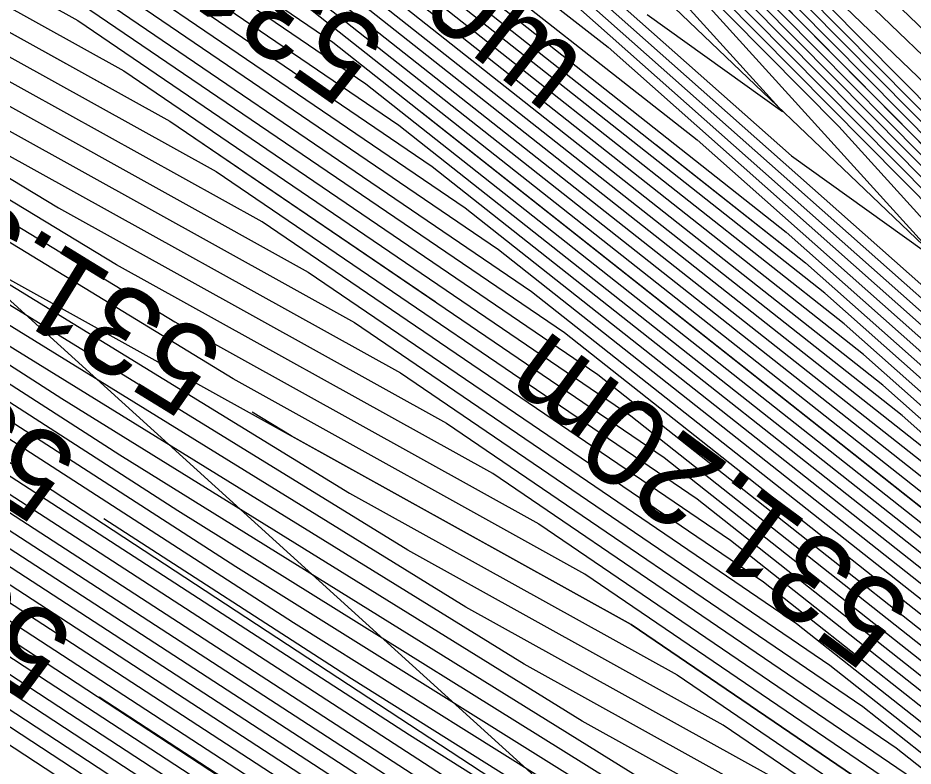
# Model space of a CAD drawing. Extents: x -866683 to -866410, y -1041951 to -1040252.
# Drawn here: x -866436.676 to -866433.64, y -1041922.966 to -1041920.429 of the extents above; entities that cross this region are included whole.
import ezdxf

# ---------------------------------------------------------------- set-up
doc = ezdxf.new("R2010")
doc.units = 0
for name, color, linetype in [('BREAKLINE', 7, 'Continuous'), ('V-HL', 7, 'Continuous'), ('V-VEDL', 7, 'Continuous'), ('V_po_cm', 7, 'Continuous')]:
    doc.layers.add(name, color=color, linetype=linetype)

msp = doc.modelspace()

# ---------------------------------------------------------------- linework, layer by layer
at = {"layer": 'BREAKLINE'}
for points in [[(-866445.626, -1041911.77), (-866438.844, -1041916.202), (-866428.169, -1041926.387)], [(-866430.202, -1041927.282), (-866445.247, -1041913.64), (-866449.543, -1041926.354), (-866449.641, -1041934.033), (-866450.183, -1041936.864), (-866452.267, -1041937.851), (-866451.576, -1041945.087)]]:
    msp.add_lwpolyline(points, dxfattribs=at)
at = {"layer": 'V-HL'}
for points in [[(-866432.13, -1041922.3514), (-866435.3498, -1041919.1014), (-866436.3778, -1041918.1143)], [(-866435.9248, -1041919.7422), (-866434.0049, -1041921.2589), (-866431.3462, -1041923.6159)]]:
    msp.add_lwpolyline(points, dxfattribs=at)
at = {"layer": 'V-VEDL'}
for points in [[(-866449.345, -1041907.5366), (-866448.9556, -1041907.8532), (-866448.4862, -1041908.0339), (-866448.3105, -1041908.3809), (-866448.4285, -1041908.8942), (-866448.8402, -1041909.5738), (-866449.0019, -1041910.1655), (-866448.9134, -1041910.6692), (-866448.5749, -1041911.085), (-866448.5335, -1041911.4362), (-866448.7893, -1041911.7228), (-866449.3421, -1041911.9448), (-866449.4057, -1041912.585), (-866448.98, -1041913.6435), (-866448.0652, -1041915.1203), (-866447.345, -1041916.0757), (-866446.8195, -1041916.5099), (-866446.4887, -1041916.4228), (-866444.7099, -1041917.3864), (-866441.483, -1041919.4008), (-866432.1333, -1041925.5308)], [(-866446.5999, -1041908.6762), (-866447.0916, -1041908.5269), (-866447.2852, -1041908.4542), (-866447.4265, -1041908.3834), (-866447.5156, -1041908.3147), (-866447.7197, -1041908.5079), (-866448.039, -1041908.963), (-866448.4735, -1041909.6802), (-866448.6281, -1041910.3241), (-866448.5029, -1041910.8948), (-866448.0979, -1041911.3922), (-866447.9787, -1041911.7844), (-866448.1452, -1041912.0714), (-866448.5975, -1041912.253), (-866448.6496, -1041912.7768), (-866448.3013, -1041913.6429), (-866447.5528, -1041914.8511), (-866446.9635, -1041915.6329), (-866446.5336, -1041915.9881), (-866446.2629, -1041915.9168), (-866444.8075, -1041916.7053), (-866442.1674, -1041918.3533), (-866434.5176, -1041923.3688)], [(-866441.6705, -1041916.8829), (-866437.7247, -1041919.072), (-866435.6089, -1041920.5114), (-866433.3503, -1041922.2956), (-866428.5474, -1041926.5536)], [(-866439.2862, -1041919.0449), (-866436.1607, -1041920.7789), (-866434.4848, -1041921.919), (-866432.6958, -1041923.3322), (-866428.8914, -1041926.705)], [(-866436.9019, -1041921.2069), (-866434.5968, -1041922.4857), (-866433.3607, -1041923.3266), (-866432.0413, -1041924.3689), (-866429.2354, -1041926.8565)]]:
    msp.add_lwpolyline(points, dxfattribs=at)
at = {"layer": 'V_po_cm'}
msp.add_lwpolyline([(-866447.3599, -1041911.0448), (-866445.9513, -1041912.7749), (-866444.619, -1041913.8303), (-866442.6588, -1041915.0759), (-866440.0707, -1041916.5117), (-866437.6107, -1041918.1202), (-866435.2789, -1041919.9012), (-866433.0752, -1041921.8549), (-866432.4602, -1041922.2952), (-866433.4339, -1041921.2221), (-866435.9962, -1041918.6357), (-866438.0089, -1041916.6902), (-866439.4718, -1041915.3858), (-866440.3849, -1041914.7224), (-866441.4494, -1041913.9281), (-866442.665, -1041913.0029), (-866444.032, -1041911.9468), (-866445.0847, -1041911.1336), (-866445.8231, -1041910.5632), (-866446.2472, -1041910.2357), (-866446.6064, -1041910.1437), (-866446.9008, -1041910.2871)], close=True, dxfattribs=at)
for points in [[(-866449.4813, -1041912.5658), (-866449.0479, -1041913.6436), (-866448.1164, -1041915.1472), (-866447.3831, -1041916.12), (-866446.8481, -1041916.5621), (-866446.5112, -1041916.4734), (-866444.7001, -1041917.4545), (-866441.4146, -1041919.5055), (-866436.6547, -1041922.6262), (-866433.3844, -1041924.7606), (-866431.6036, -1041925.9086), (-866431.3124, -1041926.0701), (-866431.0001, -1041926.2826), (-866430.6667, -1041926.546), (-866429.9578, -1041927.1745)], [(-866449.3301, -1041912.6042), (-866448.9122, -1041913.6435), (-866448.0139, -1041915.0933), (-866447.3068, -1041916.0314), (-866446.7909, -1041916.4577), (-866446.4661, -1041916.3722), (-866444.7196, -1041917.3183), (-866441.5514, -1041919.296), (-866436.9616, -1041922.3053), (-866433.7773, -1041924.3805), (-866431.9985, -1041925.5217), (-866431.6252, -1041925.7288), (-866431.2249, -1041926.0011), (-866430.7976, -1041926.3386), (-866429.889, -1041927.1442)], [(-866429.8546, -1041927.129), (-866430.8631, -1041926.2349), (-866431.3373, -1041925.8603), (-866431.7816, -1041925.5581), (-866432.1959, -1041925.3282), (-866433.9737, -1041924.1905), (-866437.115, -1041922.1448), (-866441.6199, -1041919.1913), (-866444.7294, -1041917.2502), (-866446.4435, -1041916.3216), (-866446.7623, -1041916.4055), (-866447.2687, -1041915.9871), (-866447.9627, -1041915.0664), (-866448.8443, -1041913.6434), (-866449.2545, -1041912.6234)], [(-866429.8202, -1041927.1139), (-866430.9285, -1041926.1313), (-866431.4498, -1041925.7195), (-866431.938, -1041925.3874), (-866432.3933, -1041925.1348), (-866434.1701, -1041924.0005), (-866437.2685, -1041921.9844), (-866441.6883, -1041919.0865), (-866444.7391, -1041917.1821), (-866446.4209, -1041916.271), (-866446.7337, -1041916.3534), (-866447.2305, -1041915.9429), (-866447.9114, -1041915.0395), (-866448.7764, -1041913.6433), (-866449.1788, -1041912.6426)], [(-866449.3873, -1041913.6439), (-866448.3726, -1041915.2817), (-866447.5738, -1041916.3414), (-866446.991, -1041916.823), (-866446.6241, -1041916.7264), (-866444.6513, -1041917.7951), (-866441.0724, -1041920.0292), (-866435.8875, -1041923.4286), (-866432.4023, -1041925.7108), (-866430.6166, -1041926.8758), (-866430.5304, -1041926.9236), (-866430.4381, -1041926.9864), (-866430.3395, -1041927.0643), (-866430.1298, -1041927.2502)], [(-866430.0954, -1041927.2351), (-866430.4049, -1041926.9606), (-866430.5505, -1041926.8456), (-866430.6868, -1041926.7529), (-866430.814, -1041926.6823), (-866432.5987, -1041925.5207), (-866436.041, -1041923.2681), (-866441.1408, -1041919.9245), (-866444.661, -1041917.727), (-866446.6015, -1041916.6758), (-866446.9624, -1041916.7708), (-866447.5357, -1041916.2972), (-866448.3213, -1041915.2548), (-866449.3194, -1041913.6438)], [(-866449.2515, -1041913.6438), (-866448.2701, -1041915.2279), (-866447.4975, -1041916.2529), (-866446.9338, -1041916.7186), (-866446.579, -1041916.6252), (-866444.6708, -1041917.6589), (-866441.2093, -1041919.8197), (-866436.1944, -1041923.1077), (-866432.7951, -1041925.3307), (-866431.0114, -1041926.4889), (-866430.8432, -1041926.5822), (-866430.6629, -1041926.7049), (-866430.4704, -1041926.857), (-866430.061, -1041927.2199)], [(-866430.0266, -1041927.2048), (-866430.5358, -1041926.7533), (-866430.7753, -1041926.5641), (-866430.9996, -1041926.4115), (-866431.2088, -1041926.2954), (-866432.9916, -1041925.1407), (-866436.3479, -1041922.9472), (-866441.2777, -1041919.715), (-866444.6806, -1041917.5908), (-866446.5564, -1041916.5746), (-866446.9052, -1041916.6664), (-866447.4594, -1041916.2086), (-866448.2189, -1041915.201), (-866449.1837, -1041913.6437)], [(-866449.1158, -1041913.6437), (-866448.1676, -1041915.1741), (-866447.4212, -1041916.1643), (-866446.8766, -1041916.6143), (-866446.5338, -1041916.524), (-866444.6903, -1041917.5227), (-866441.3461, -1041919.6102), (-866436.5013, -1041922.7867), (-866433.188, -1041924.9506), (-866431.4062, -1041926.102), (-866431.156, -1041926.2408), (-866430.8877, -1041926.4234), (-866430.6013, -1041926.6496), (-866429.9922, -1041927.1896)], [(-866436.6255, -1041917.6643), (-866433.1945, -1041921.1275)], [(-866427.7667, -1041926.0662), (-866436.2098, -1041917.9718)], [(-866436.3065, -1041918.0236), (-866432.1894, -1041922.1794)], [(-866429.5106, -1041926.9776), (-866431.5176, -1041925.1983), (-866432.4615, -1041924.4527), (-866433.3456, -1041923.8512), (-866434.17, -1041923.3938), (-866435.9379, -1041922.2901), (-866438.6494, -1041920.5402), (-866442.3042, -1041918.1439)], [(-866429.545, -1041926.9928), (-866431.4522, -1041925.3019), (-866432.349, -1041924.5935), (-866433.1892, -1041924.0219), (-866433.9726, -1041923.5873), (-866435.7415, -1041922.4802), (-866438.4959, -1041920.7006), (-866442.2358, -1041918.2486)], [(-866435.9876, -1041918.3828), (-866431.1843, -1041923.2313)], [(-866435.581, -1041919.5877), (-866433.5641, -1041921.3758), (-866433.0012, -1041921.7788), (-866433.8924, -1041920.7967), (-866436.2376, -1041918.4294)], [(-866429.6138, -1041927.023), (-866431.3213, -1041925.5093), (-866432.1242, -1041924.875), (-866432.8764, -1041924.3633), (-866433.5778, -1041923.9742), (-866435.3487, -1041922.8603), (-866438.1891, -1041921.0216), (-866442.0989, -1041918.4581)], [(-866437.2281, -1041918.5416), (-866434.6746, -1041920.5282), (-866432.0974, -1041922.813), (-866431.3782, -1041923.3279), (-866432.5169, -1041922.073), (-866435.5136, -1041919.0482)], [(-866429.6482, -1041927.0382), (-866431.2558, -1041925.6129), (-866432.0118, -1041925.0157), (-866432.72, -1041924.534), (-866433.3804, -1041924.1676), (-866435.1522, -1041923.0503), (-866438.0356, -1041921.182), (-866442.0305, -1041918.5628)], [(-866441.9621, -1041918.6676), (-866437.8822, -1041921.3425), (-866434.9558, -1041923.2403), (-866433.183, -1041924.361), (-866432.5636, -1041924.7046), (-866431.8994, -1041925.1565), (-866431.1904, -1041925.7166), (-866429.6826, -1041927.0533)], [(-866437.0368, -1041918.7523), (-866434.3725, -1041920.8417), (-866431.6085, -1041923.292), (-866430.8372, -1041923.8443), (-866432.0584, -1041922.4984), (-866435.2722, -1041919.2544)], [(-866435.6687, -1041918.7421), (-866430.1792, -1041924.2832)], [(-866429.717, -1041927.0685), (-866431.1249, -1041925.8203), (-866431.787, -1041925.2973), (-866432.4072, -1041924.8753), (-866432.9855, -1041924.5545), (-866434.7594, -1041923.4304), (-866437.7288, -1041921.503), (-866441.8936, -1041918.7723)], [(-866434.9767, -1041920.2147), (-866432.5863, -1041922.3339), (-866431.9192, -1041922.8115), (-866432.9754, -1041921.6475), (-866435.7549, -1041918.8419)], [(-866429.7514, -1041927.0836), (-866431.0594, -1041925.9239), (-866431.6746, -1041925.438), (-866432.2508, -1041925.046), (-866432.7881, -1041924.7479), (-866434.563, -1041923.6204), (-866437.5753, -1041921.6634), (-866441.8252, -1041918.877)], [(-866436.8455, -1041918.963), (-866434.0703, -1041921.1552), (-866431.1197, -1041923.7711), (-866430.2962, -1041924.3606), (-866431.6, -1041922.9238), (-866435.0309, -1041919.4606)], [(-866429.7858, -1041927.0988), (-866430.994, -1041926.0276), (-866431.5622, -1041925.5788), (-866432.0944, -1041925.2167), (-866432.5907, -1041924.9414), (-866434.3665, -1041923.8104), (-866437.4219, -1041921.8239), (-866441.7568, -1041918.9818)], [(-866427.817, -1041926.1063), (-866435.2047, -1041919.0237)], [(-866429.201, -1041926.8413), (-866432.1067, -1041924.2653), (-866433.4731, -1041923.1858), (-866434.7532, -1041922.315), (-866435.9468, -1041921.6529), (-866437.7058, -1041920.5798), (-866440.0303, -1041919.0959)], [(-866438.8617, -1041919.234), (-866437.7235, -1041919.9119), (-866436.1607, -1041920.7789), (-866435.2618, -1041921.3904)], [(-866437.5683, -1041919.2427), (-866435.4965, -1041920.6521), (-866433.2849, -1041922.3992), (-866428.5818, -1041926.5687)], [(-866428.2378, -1041926.4173), (-866433.9394, -1041921.3625), (-866436.6206, -1041919.2445)], [(-866435.8831, -1041919.2742), (-866434.053, -1041920.8968), (-866433.5422, -1041921.2624), (-866434.3509, -1041920.3712)], [(-866428.2722, -1041926.4324), (-866433.874, -1041921.4662), (-866436.5082, -1041919.3853)], [(-866439.7234, -1041919.4169), (-866437.3129, -1041920.9599), (-866435.5519, -1041922.0397), (-866434.4404, -1041922.6564), (-866433.2483, -1041923.4674), (-866431.9758, -1041924.4726), (-866429.2698, -1041926.8716)], [(-866437.4119, -1041919.4134), (-866435.3841, -1041920.7929), (-866433.2194, -1041922.5029), (-866428.6162, -1041926.5839)], [(-866438.8843, -1041919.4396), (-866437.1312, -1041920.4922), (-866435.6915, -1041921.2909), (-866434.1476, -1041922.3413), (-866432.4994, -1041923.6432), (-866428.9946, -1041926.7505)], [(-866438.1183, -1041919.525), (-866436.4735, -1041920.4375), (-866434.7097, -1041921.6375), (-866432.8267, -1041923.1249), (-866428.8226, -1041926.6747)], [(-866428.3066, -1041926.4476), (-866433.8085, -1041921.5699), (-866436.3958, -1041919.526)], [(-866429.3042, -1041926.8867), (-866431.9103, -1041924.5763), (-866433.1359, -1041923.6081), (-866434.284, -1041922.8271), (-866435.3545, -1041922.2332), (-866437.1165, -1041921.1499), (-866439.57, -1041919.5773)], [(-866428.6506, -1041926.599), (-866433.154, -1041922.6066), (-866435.2717, -1041920.9337), (-866437.2555, -1041919.5841)], [(-866438.6879, -1041919.6296), (-866436.9338, -1041920.6857), (-866435.5351, -1041921.4616), (-866434.0352, -1041922.482), (-866432.434, -1041923.7469), (-866429.029, -1041926.7656)], [(-866428.341, -1041926.4627), (-866433.7431, -1041921.6735), (-866436.2834, -1041919.6668)], [(-866437.9209, -1041919.7184), (-866436.3171, -1041920.6082), (-866434.5973, -1041921.7782), (-866432.7612, -1041923.2286), (-866428.857, -1041926.6899)], [(-866429.3386, -1041926.9019), (-866431.8449, -1041924.6799), (-866433.0235, -1041923.7489), (-866434.1276, -1041922.9978), (-866435.1571, -1041922.4266), (-866436.9201, -1041921.34), (-866439.4165, -1041919.7378)], [(-866428.685, -1041926.6142), (-866433.0885, -1041922.7102), (-866435.1593, -1041921.0744), (-866437.0991, -1041919.7548)], [(-866438.4915, -1041919.8197), (-866436.7364, -1041920.8791), (-866435.3788, -1041921.6323), (-866433.9228, -1041922.6228), (-866432.3685, -1041923.8506), (-866429.0634, -1041926.7807)], [(-866428.3754, -1041926.4779), (-866433.6776, -1041921.7772), (-866436.171, -1041919.8076)], [(-866429.373, -1041926.917), (-866431.7794, -1041924.7836), (-866432.9111, -1041923.8896), (-866433.9712, -1041923.1685), (-866434.9597, -1041922.6201), (-866436.7237, -1041921.53), (-866439.2631, -1041919.8983)], [(-866428.7194, -1041926.6293), (-866433.0231, -1041922.8139), (-866435.0469, -1041921.2152), (-866436.9427, -1041919.9254)], [(-866428.4098, -1041926.493), (-866433.6121, -1041921.8809), (-866436.0586, -1041919.9483)], [(-866434.5418, -1041920.4177), (-866434.0832, -1041920.7461), (-866434.8093, -1041919.9458)], [(-866431.5518, -1041922.935), (-866434.5077, -1041919.9514)], [(-866438.2951, -1041920.0097), (-866436.539, -1041921.0725), (-866435.2224, -1041921.803), (-866433.8104, -1041922.7636), (-866432.3031, -1041923.9542), (-866429.0978, -1041926.7959)], [(-866429.4074, -1041926.9322), (-866431.714, -1041924.8873), (-866432.7987, -1041924.0304), (-866433.8148, -1041923.3392), (-866434.7623, -1041922.8135), (-866436.5272, -1041921.72), (-866439.1097, -1041920.0587)], [(-866428.4442, -1041926.5082), (-866433.5467, -1041921.9845), (-866435.9462, -1041920.0891)], [(-866427.8673, -1041926.1464), (-866434.1996, -1041920.0756)], [(-866437.5261, -1041920.1053), (-866436.0043, -1041920.9496), (-866434.3724, -1041922.0597), (-866432.6303, -1041923.4359), (-866428.9258, -1041926.7202)], [(-866436.7863, -1041920.0961), (-866434.9345, -1041921.3559), (-866432.9576, -1041922.9176), (-866428.7538, -1041926.6444)], [(-866429.1322, -1041926.811), (-866432.2376, -1041924.0579), (-866433.698, -1041922.9043), (-866435.066, -1041921.9737), (-866436.3416, -1041921.266), (-866438.0986, -1041920.1998)], [(-866438.9562, -1041920.2192), (-866436.3308, -1041921.9101), (-866434.5649, -1041923.0069), (-866433.6584, -1041923.5098), (-866432.6863, -1041924.1712), (-866431.6485, -1041924.9909), (-866429.4418, -1041926.9473)], [(-866428.4786, -1041926.5233), (-866433.4812, -1041922.0882), (-866435.8338, -1041920.2298)], [(-866428.7882, -1041926.6596), (-866432.8922, -1041923.0212), (-866434.8221, -1041921.4967), (-866436.6299, -1041920.2668)], [(-866428.9602, -1041926.7353), (-866432.5649, -1041923.5396), (-866434.26, -1041922.2005), (-866435.8479, -1041921.1202), (-866437.3287, -1041920.2988)], [(-866429.4762, -1041926.9625), (-866431.5831, -1041925.0946), (-866432.5739, -1041924.3119), (-866433.502, -1041923.6805), (-866434.3674, -1041923.2004), (-866436.1344, -1041922.1001), (-866438.8028, -1041920.3797)], [(-866437.9022, -1041920.3898), (-866436.1442, -1041921.4594), (-866434.9096, -1041922.1444), (-866433.5856, -1041923.0451), (-866432.1722, -1041924.1616), (-866429.1666, -1041926.8262)], [(-866428.513, -1041926.5384), (-866433.4158, -1041922.1919), (-866435.7214, -1041920.3706)], [(-866432.0739, -1041923.4272), (-866433.3503, -1041922.2956), (-866435.3071, -1041920.7498)], [(-866434.5125, -1041920.8579), (-866434.0049, -1041921.2589), (-866431.3462, -1041923.6159)], [(-866432.3948, -1041924.0896), (-866433.3607, -1041923.3266), (-866434.5968, -1041922.4857), (-866435.7493, -1041921.8463), (-866435.8822, -1041921.7651)], [(-866432.8177, -1041924.3389), (-866433.0328, -1041924.1926), (-866433.7752, -1041923.7807), (-866435.5451, -1041922.6702), (-866436.385, -1041922.1271)], [(-866432.88, -1041925.0213), (-866433.5808, -1041924.5706), (-866436.4008, -1041922.7314)]]:
    msp.add_lwpolyline(points, dxfattribs=at)

# ---------------------------------------------------------------- texts
for s, rotation, p in [('531.00m', 321.6932, (-866436.1113, -1041919.786)), ('531.10m', 145.0263, (-866435.4113, -1041920.4939)), ('531.30m', 148.4452, (-866435.9622, -1041921.5399)), ('531.40m', 147.1085, (-866436.4555, -1041921.9028)), ('531.20m', 143.5171, (-866433.6296, -1041922.4108)), ('531.50m', 146.7817, (-866436.4701, -1041922.5068))]:
    msp.add_text(s, height=0.3, rotation=rotation, dxfattribs=at).set_placement(p)

doc.saveas('drawing.dxf')
